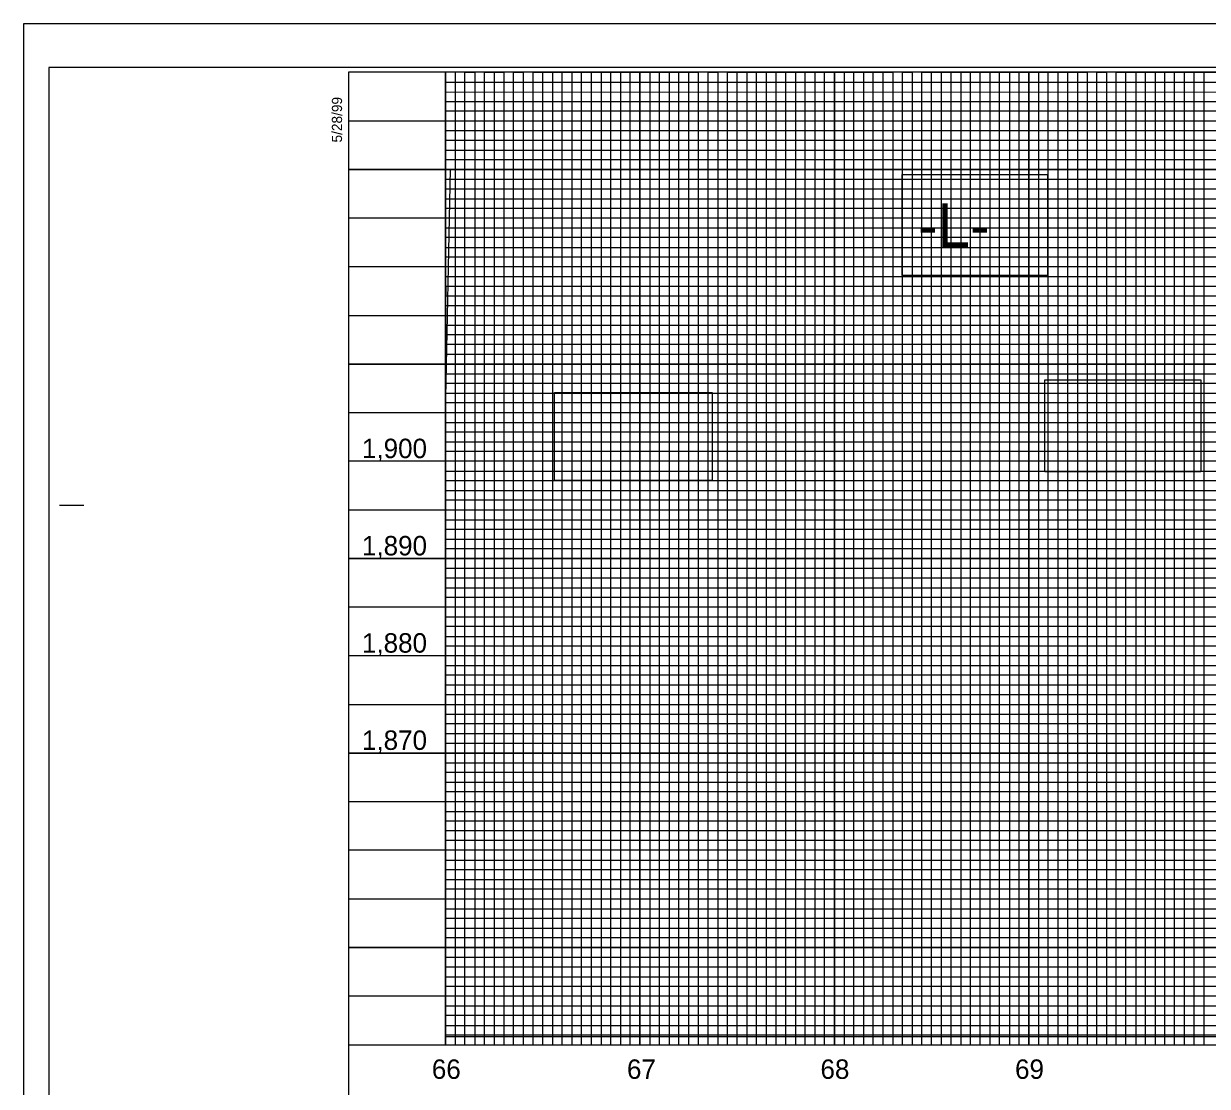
# Model space of a CAD drawing. Extents: x 557032 to 558840, y 515971 to 517218.
# Drawn here: x 557032 to 557641, y 516672 to 517218 of the extents above; entities that cross this region are included whole.
import ezdxf

# ---------------------------------------------------------------- set-up
doc = ezdxf.new("R2010")
doc.units = 0
for name, color, linetype in [('Exist Vertical Profile Horizontal Axis Label Major', 7, 'Continuous'), ('Exist Vertical Profile Vertical Axis Label', 7, 'Continuous'), ('Prop Vertical Profile Curve Label', 7, 'Continuous'), ('Prop Vertical Profile Grade Label', 7, 'Continuous'), ('Prop VPI Label', 7, 'Continuous'), ('Scratch_Level_5', 7, 'Continuous'), ('Sheet Cutting Line CELL', 7, 'Continuous'), ('Sheet DOT Grid CELL', 7, 'Continuous'), ('Sheet Layout Profile Border Port 1', 7, 'Continuous'), ('Sheet Plot Border Inside CELL', 7, 'Continuous'), ('Sheet Plot Border Outside CELL', 7, 'Continuous'), ('Sheet Profile CELL', 7, 'Continuous'), ('Sheet Profile Grid Major CELL', 7, 'Continuous'), ('Sheet Profile Grid Middle CELL', 7, 'Continuous'), ('Sheet Profile Grid Minor CELL', 7, 'Continuous')]:
    doc.layers.add(name, color=color, linetype=linetype)

msp = doc.modelspace()

# ---------------------------------------------------------------- linework, layer by layer
at = {"layer": 'Prop Vertical Profile Curve Label'}
msp.add_lwpolyline([(557484.34, 517140.65), (557559.1, 517140.65), (557559.1, 517088.71), (557484.34, 517088.71)], close=True, dxfattribs=at)
at = {"layer": 'Prop Vertical Profile Grade Label'}
for points in [[(557484.34, 517140.65), (557559.1, 517140.65), (557559.1, 517088.71), (557484.34, 517088.71)], [(557557.73, 517035.14), (557637.96, 517035.14), (557637.96, 516987.79), (557557.73, 516987.79)], [(557305.42, 517028.62), (557386.51, 517028.62), (557386.51, 516983.35), (557305.42, 516983.35)]]:
    msp.add_lwpolyline(points, close=True, dxfattribs=at)
at = {"layer": 'Prop VPI Label'}
msp.add_lwpolyline([(557484.34, 517140.65), (557559.1, 517140.65), (557559.1, 517088.71), (557484.34, 517088.71)], close=True, dxfattribs=at)
at = {"layer": 'Scratch_Level_5'}
msp.add_lwpolyline([(557249.45, 516896.35), (557249.45, 517017.65), (557251.99, 517143.31), (557976.89, 517143.33), (557976.9, 516697.32), (557249.46, 516697.3)], close=True, dxfattribs=at)
at = {"layer": 'Sheet Cutting Line CELL'}
for p, q in [((558716.45, 517218.17), (557032.45, 517218.17)), ((557032.45, 517218.17), (557032.45, 516118.17))]:
    msp.add_line(p, q, dxfattribs=at)
at = {"layer": 'Sheet DOT Grid CELL'}
for p, q in [((557249.45, 516693.17), (557249.45, 517193.17)), ((557299.45, 516693.17), (557299.45, 517193.17)), ((557349.45, 516693.17), (557349.45, 517193.17)), ((557399.45, 516693.17), (557399.45, 517193.17)), ((557449.45, 516693.17), (557449.45, 517193.17)), ((557499.45, 516693.17), (557499.45, 517193.17)), ((557549.45, 516693.17), (557549.45, 517193.17)), ((557599.45, 516693.17), (557599.45, 517193.17)), ((558499.4, 517143.17), (557199.45, 517143.17)), ((558499.4, 517093.17), (557199.45, 517093.17)), ((558499.45, 517043.17), (557199.45, 517043.17)), ((558699.45, 516993.17), (557199.45, 516993.17)), ((558699.45, 516943.17), (557199.45, 516943.17)), ((558699.45, 516893.17), (557199.45, 516893.17)), ((558699.45, 516843.17), (557199.45, 516843.17)), ((558699.45, 516793.17), (557199.45, 516793.17)), ((558699.45, 516743.17), (557199.45, 516743.17))]:
    msp.add_line(p, q, dxfattribs=at)
at = {"layer": 'Sheet Layout Profile Border Port 1'}
msp.add_lwpolyline([(557249.45, 517032.12), (557249.45, 516693.17), (558649.45, 516693.17), (558649.45, 517032.12)], dxfattribs=at)
at = {"layer": 'Sheet Plot Border Inside CELL'}
msp.add_lwpolyline([(557045.45, 516140.62), (558711.95, 516140.62), (558711.95, 517195.72), (557045.45, 517195.72)], close=True, dxfattribs=at)
at = {"layer": 'Sheet Plot Border Outside CELL'}
msp.add_lwpolyline([(557032.45, 516118.17), (558716.45, 516118.17), (558716.45, 517218.17), (557032.45, 517218.17)], close=True, dxfattribs=at)
at = {"layer": 'Sheet Profile CELL'}
for p, q in [((557050.95, 516970.67), (557063.45, 516970.67)), ((557199.45, 516693.17), (558699.45, 516693.17))]:
    msp.add_line(p, q, dxfattribs=at)
msp.add_lwpolyline([(558699.45, 517193.17), (557199.45, 517193.17), (557199.45, 516143.17), (558699.45, 516143.17)], close=True, dxfattribs=at)
at = {"layer": 'Sheet Profile Grid Major CELL'}
for points in [[(557249.45, 517193.17), (557249.45, 516693.17), (557299.45, 516693.17), (557299.45, 517193.17), (557349.45, 517193.17), (557349.45, 516693.17), (557399.45, 516693.17), (557399.45, 517193.17), (557449.45, 517193.17), (557449.45, 516693.17), (557499.45, 516693.17), (557499.45, 517193.17), (557549.45, 517193.17), (557549.45, 516693.17), (557599.45, 516693.17), (557599.45, 517193.17), (557649.45, 517193.17)], [(557199.45, 517143.17), (558499.45, 517143.17)], [(558499.45, 517093.17), (557199.45, 517093.17), (557199.45, 517043.17), (558499.45, 517043.17)], [(558699.45, 516993.17), (557199.45, 516993.17), (557199.45, 516943.17), (558699.45, 516943.17)], [(558699.45, 516893.17), (557199.45, 516893.17), (557199.45, 516843.17), (558699.45, 516843.17)], [(558699.45, 516793.17), (557199.45, 516793.17), (557199.45, 516793.17), (557199.45, 516743.17), (558699.45, 516743.17)]]:
    msp.add_lwpolyline(points, dxfattribs=at)
at = {"layer": 'Sheet Profile Grid Middle CELL'}
msp.add_line((557199.45, 517168.17), (558499.4, 517168.17), dxfattribs=at)
for points in [[(557274.45, 517193.17), (557274.45, 516693.17), (557324.45, 516693.17), (557324.45, 517193.17), (557374.45, 517193.17), (557374.45, 516693.17), (557424.45, 516693.17), (557424.45, 517193.17), (557474.45, 517193.17), (557474.45, 516693.17), (557524.45, 516693.17), (557524.45, 517193.17), (557574.45, 517193.17), (557574.45, 516693.17), (557624.45, 516693.17), (557624.45, 517193.17), (557674.45, 517193.17)], [(558499.45, 517118.17), (557199.45, 517118.17), (557199.45, 517068.17), (558499.45, 517068.17)], [(558699.45, 517018.17), (557199.45, 517018.17), (557199.45, 516968.17), (558524.45, 516968.17)], [(558699.45, 516918.17), (557199.45, 516918.17), (557199.45, 516868.17), (558699.45, 516868.17)], [(558699.45, 516818.17), (557199.45, 516818.17), (557199.45, 516768.17), (558699.45, 516768.17)], [(558699.45, 516718.17), (557199.45, 516718.17)]]:
    msp.add_lwpolyline(points, dxfattribs=at)
at = {"layer": 'Sheet Profile Grid Minor CELL'}
for p, q in [((557249.45, 517188.17), (558499.45, 517188.17)), ((557249.45, 517183.17), (557249.45, 517183.17)), ((558499.45, 517183.17), (557249.45, 517182.82)), ((557249.45, 517178.17), (558499.45, 517178.17)), ((558499.4, 517058.17), (557249.45, 517058.17)), ((558499.45, 517053.17), (557249.45, 517053.17)), ((558499.45, 517048.17), (557249.45, 517048.17)), ((557249.45, 517038.17), (558499.45, 517038.17)), ((558499.45, 517033.17), (557249.45, 517033.17)), ((557249.45, 517028.17), (558649.45, 517028.17)), ((558649.45, 517008.17), (557249.45, 517008.17)), ((557249.45, 517003.17), (558649.45, 517003.17)), ((558649.45, 516983.17), (557249.45, 516983.17)), ((557249.45, 516978.17), (558649.45, 516978.17)), ((558649.45, 516958.17), (557249.45, 516958.17)), ((557249.45, 516953.17), (558649.45, 516953.17)), ((558649.45, 516948.17), (557249.45, 516948.17)), ((557249.45, 516938.17), (558649.45, 516938.17)), ((558649.45, 516933.17), (557249.45, 516933.17)), ((557249.45, 516928.17), (558649.45, 516928.17)), ((558649.45, 516923.17), (557249.45, 516923.17)), ((557249.45, 516913.17), (558649.45, 516913.17)), ((558649.45, 516908.17), (557249.45, 516908.17)), ((557249.45, 516903.17), (558649.45, 516903.17)), ((558649.45, 516898.17), (557249.45, 516898.17)), ((557249.45, 516888.17), (558649.45, 516888.17)), ((558649.45, 516883.17), (557249.45, 516883.17)), ((557249.45, 516878.17), (558649.45, 516878.17)), ((558649.45, 516873.17), (557249.45, 516873.17)), ((557249.45, 516863.17), (558649.45, 516863.17)), ((558649.45, 516858.17), (557249.45, 516858.17)), ((557249.45, 516853.17), (558649.45, 516853.17)), ((558649.45, 516848.17), (557249.45, 516848.17)), ((557249.45, 516838.17), (558649.45, 516838.17)), ((558649.45, 516833.17), (557249.45, 516833.17)), ((557249.45, 516828.17), (558649.45, 516828.17)), ((558649.45, 516823.17), (557249.45, 516823.17)), ((557249.45, 516813.17), (558649.45, 516813.17)), ((558649.45, 516808.17), (557249.45, 516808.17)), ((558649.45, 516803.17), (557249.45, 516803.17)), ((558649.45, 516798.17), (557249.45, 516798.17)), ((557249.45, 516788.17), (558649.45, 516788.17)), ((558649.45, 516783.17), (557249.45, 516783.17)), ((557249.45, 516778.17), (558649.45, 516778.17)), ((558649.45, 516773.17), (557249.45, 516773.17)), ((557249.45, 516763.17), (558649.45, 516763.17)), ((558649.45, 516758.17), (557249.45, 516758.17)), ((557249.45, 516753.17), (558649.45, 516753.17)), ((558649.45, 516748.17), (557249.45, 516748.17)), ((557249.45, 516738.17), (558649.45, 516738.17)), ((558649.45, 516733.17), (557249.45, 516733.17)), ((557249.45, 516728.17), (558649.45, 516728.17)), ((558649.45, 516723.17), (557249.45, 516723.17)), ((557249.45, 516713.17), (558649.45, 516713.17)), ((558649.45, 516708.17), (557249.45, 516708.17)), ((557249.45, 516703.17), (558649.45, 516703.17))]:
    msp.add_line(p, q, dxfattribs=at)
for points in [[(557254.45, 517193.17), (557254.45, 516693.17), (557259.45, 516693.17), (557259.45, 517193.17), (557264.45, 517193.17), (557264.45, 516693.17), (557269.45, 516693.17), (557269.45, 517193.17), (557279.45, 517193.17), (557279.45, 516693.17), (557284.45, 516693.17), (557284.45, 517193.17), (557289.45, 517193.17), (557289.45, 516693.17), (557294.45, 516693.17), (557304.45, 516693.17), (557309.45, 516693.17), (557309.45, 517193.17), (557314.45, 517193.17), (557314.45, 516693.17), (557319.45, 516693.17), (557319.45, 517193.17), (557329.45, 517193.17), (557329.45, 516693.17), (557334.45, 516693.17), (557334.45, 517193.17), (557339.45, 517193.17), (557339.45, 516693.17), (557344.45, 516693.17), (557344.45, 517193.17), (557354.45, 517193.17), (557354.45, 516693.17), (557359.45, 516693.17), (557359.45, 517193.17), (557364.45, 517193.17), (557364.45, 516693.17), (557369.45, 516693.17), (557369.45, 517193.17), (557379.45, 517193.17), (557379.45, 516693.17), (557384.45, 516693.17), (557384.45, 517193.17), (557389.45, 517193.17), (557389.45, 516693.17), (557394.45, 516693.17), (557394.45, 517193.17), (557404.45, 517193.17), (557404.45, 516693.17), (557409.45, 516693.17), (557409.45, 517193.17), (557414.45, 517193.17), (557414.45, 516693.17), (557419.45, 516693.17), (557419.45, 517193.17), (557429.45, 517193.17), (557429.45, 516693.17), (557434.45, 516693.17), (557434.45, 517193.17), (557439.45, 517193.17), (557439.45, 516693.17), (557444.45, 516693.17), (557444.45, 517193.17), (557454.45, 517193.17), (557454.45, 516693.17), (557459.45, 516693.17), (557459.45, 517193.17), (557464.45, 517193.17), (557464.45, 516693.17)], [(557294.45, 516693.17), (557294.45, 517193.17), (557304.45, 517193.17), (557304.45, 516693.17)], [(557464.45, 516693.17), (557469.45, 516693.17), (557469.45, 517193.17), (557479.45, 517193.17), (557479.45, 516693.17), (557484.45, 516693.17), (557484.45, 517193.17), (557489.45, 517193.17), (557489.45, 516693.17), (557494.45, 516693.17), (557494.45, 517193.17), (557504.45, 517193.17), (557504.45, 516693.17), (557509.45, 516693.17), (557509.45, 517193.17), (557514.45, 517193.17), (557514.45, 516693.17), (557519.45, 516693.17), (557519.45, 517193.17), (557529.45, 517193.17), (557529.45, 516693.17), (557534.45, 516693.17), (557534.45, 517193.17), (557539.45, 517193.17), (557539.45, 516693.17), (557544.45, 516693.17), (557544.45, 517193.17), (557554.45, 517193.17), (557554.45, 516693.17), (557559.45, 516693.17), (557559.45, 517193.17), (557564.45, 517193.17), (557564.45, 516693.17), (557569.45, 516693.17), (557569.45, 517193.17), (557579.45, 517193.17), (557579.45, 516693.17), (557584.45, 516693.17), (557584.45, 517193.17), (557589.45, 517193.17), (557589.45, 516693.17), (557594.45, 516693.17), (557594.45, 517193.17), (557604.45, 517193.17), (557604.45, 516693.17), (557609.45, 516693.17), (557609.45, 517193.17), (557614.45, 517193.17), (557614.45, 516693.17), (557619.45, 516693.17), (557619.45, 517193.17), (557629.45, 517193.17), (557629.45, 516693.17), (557634.45, 516693.17), (557634.45, 517193.17), (557639.45, 517193.17), (557639.45, 516693.17), (557644.45, 516693.17)], [(558499.45, 517173.17), (557249.45, 517173.17), (557249.45, 517163.17), (558499.45, 517163.17)], [(558499.4, 517158.17), (557249.45, 517158.17), (557249.45, 517153.17), (558499.45, 517153.17)], [(558499.45, 517148.17), (557249.45, 517148.17), (557249.45, 517138.17), (558499.45, 517138.17)], [(558499.45, 517133.17), (557249.45, 517133.17), (557249.45, 517128.17), (558499.45, 517128.17)], [(558499.45, 517123.17), (557249.45, 517123.17), (557249.45, 517113.17), (558499.45, 517113.17)], [(558499.45, 517108.17), (557249.45, 517108.17), (557249.45, 517103.17), (558499.45, 517103.17)], [(558499.45, 517098.17), (557249.45, 517098.17), (557249.45, 517088.17), (558499.45, 517088.17)], [(558499.45, 517083.07), (557249.55, 517083.07), (557249.55, 517078.17), (558499.45, 517078.17)], [(558499.45, 517073.17), (557249.45, 517073.17), (557249.45, 517063.17), (558499.45, 517063.17)], [(558649.45, 517023.17), (557249.45, 517023.17), (557249.45, 517013.17), (558649.45, 517013.17)], [(558649.45, 516998.17), (557249.45, 516998.17), (557249.45, 516988.17), (558649.45, 516988.17)], [(558649.45, 516973.17), (557249.45, 516973.17), (557249.45, 516963.17), (558649.45, 516963.17)], [(558649.45, 516698.17), (557249.45, 516698.17)]]:
    msp.add_lwpolyline(points, dxfattribs=at)

# ---------------------------------------------------------------- texts
at = {"layer": 'Exist Vertical Profile Horizontal Axis Label Major'}
for s, p in [('66', (557242.41, 516675.67)), ('67', (557342.77, 516675.67)), ('68', (557442.3, 516675.67)), ('69', (557542.39, 516675.67))]:
    msp.add_text(s, height=10, dxfattribs=at).set_placement(p)
at = {"layer": 'Exist Vertical Profile Vertical Axis Label'}
for s, p in [('1,900', (557206.46, 516994.8)), ('1,890', (557206.46, 516944.8)), ('1,880', (557206.46, 516894.8)), ('1,870', (557206.46, 516844.8))]:
    msp.add_text(s, height=10, dxfattribs=at).set_placement(p)
at = {"layer": 'Prop Vertical Profile Grade Label'}
msp.add_text('-L-', height=22.5, dxfattribs=at).set_placement((557492.5, 517103.29))
at = {"layer": 'Sheet Profile CELL'}
msp.add_text('5/28/99', height=5.25, rotation=90, dxfattribs=at).set_placement((557196.22, 517157.08))

doc.saveas('drawing.dxf')
